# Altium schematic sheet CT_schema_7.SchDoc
size 282 x 245 mm
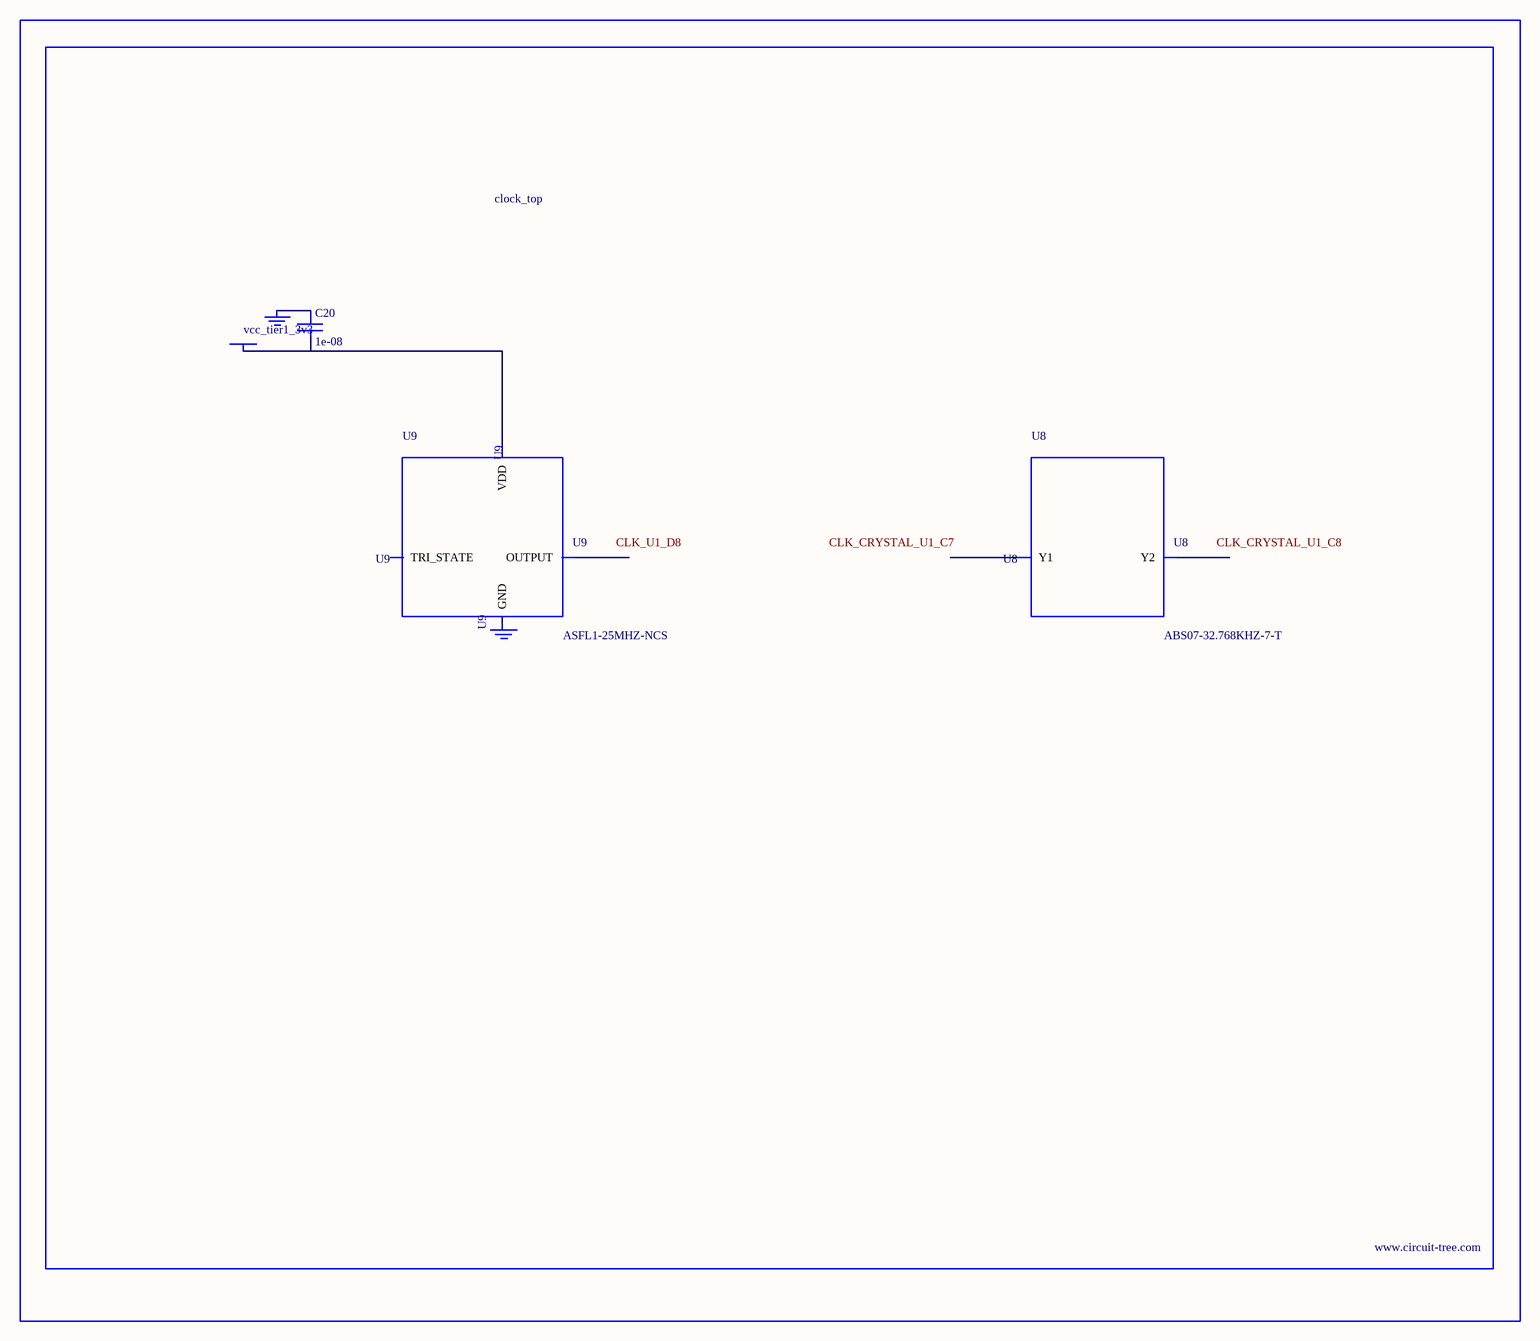
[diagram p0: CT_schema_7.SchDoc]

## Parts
BORDER6  (no value)
C20  1e-08  [C0402]
GND_INSTANCE_6_0  (no value)
GND_INSTANCE_6_1  (no value)
POWER_INSTANCE_6_0  vcc_tier1_3v3
U8  ABS07-32.768KHZ-7-T  [ABS07-32.768KHZ-7-T]
U9  ASFL1-25MHZ-NCS  [ASFL1]

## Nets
NetC20_1: C20.1 GND_INSTANCE_6_0.0(GND)
NetC20_2: C20.2 POWER_INSTANCE_6_0.0(PWR) U9.4(VDD)

Not connected (* = marked no-connect by the designer): GND_INSTANCE_6_1 0(GND); U8 1(Y1) 2(Y2); U9 1(TRI_STATE) 2(GND) 3(OUTPUT)

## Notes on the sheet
- Labels drawn without touching a wire or pin: CLK_CRYSTAL_U1_C7, CLK_CRYSTAL_U1_C8, CLK_U1_D8

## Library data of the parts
BORDER6 = BORDER_PAGE6
C20 = C0402C103K3RAC
GND_INSTANCE_6_0 GND_INSTANCE_6_1 = GND
POWER_INSTANCE_6_0 = PWR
